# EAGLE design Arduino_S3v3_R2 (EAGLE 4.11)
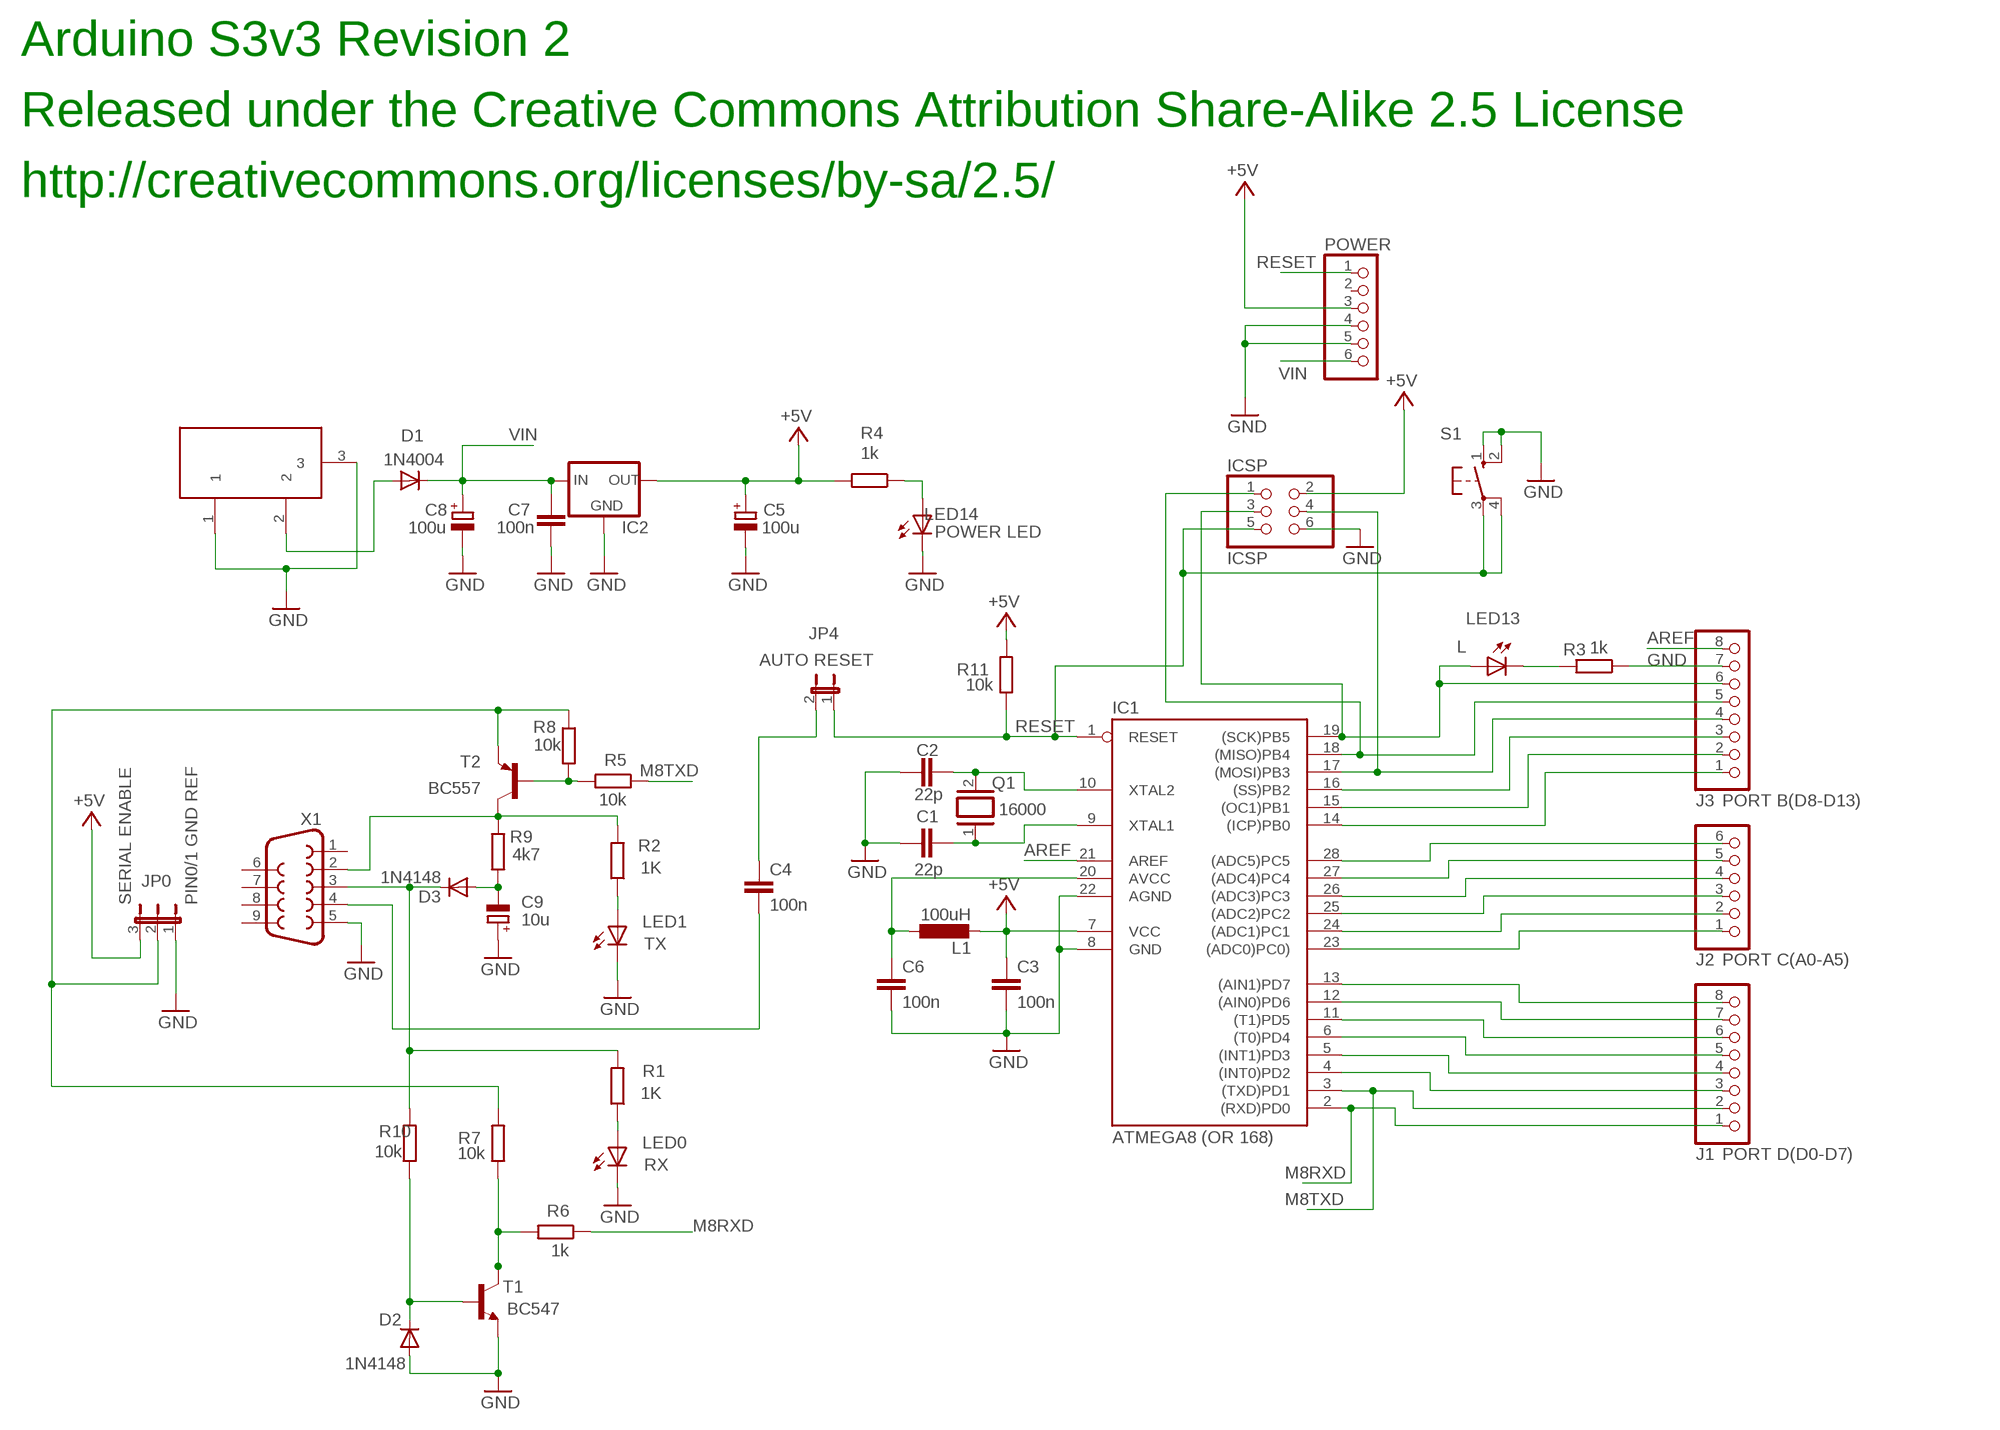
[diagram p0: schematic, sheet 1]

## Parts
C1  22p  C-EU050-025X075  [C050-025X075]
C2  22p  C-EU050-025X075  [C050-025X075]
C3  100n  C-EU050-025X075  [C050-025X075]
C4  100n  C-EU050-025X075  [C050-025X075]
C5  100u  CPOL-EUE3.5-8  [E3,5-8]
C6  100n  C-EU050-025X075  [C050-025X075]
C7  100n  C-EU050-025X075  [C050-025X075]
C8  100u  CPOL-EUE3.5-8  [E3,5-8]
C9  10u  CPOL-EUE5-6  [E5-6]
D1  1N4004  [DO41-10]
D2  1N4148  [DO35-10]
D3  1N4148  [DO35-10]
DC1  DC21MMX  [DC-21MM]
IC1  ATMEGA8 (OR 168)  AT90S4433P  [DIL28-3]
IC2  78XXL  [78XXL]
ICSP  ICSP  PINHD-2X3  [2X03]
J1  PORT D(D0-D7)  PINHD-1X8  [1X08]
J2  PORT C(A0-A5)  PINHD-1X6  [1X06]
J3  PORT B(D8-D13)  PINHD-1X8  [1X08]
JP0  JP2W  [JP2W]
JP4  AUTO RESET  JP1W  [JP1W]
L1  100uH  L-EU0207/10  [0207/10]
LED0  RX  LED3MM  [LED3MM]
LED1  TX  LED3MM  [LED3MM]
LED13  L  LED3MM  [LED3MM]
LED14  POWER LED  LED3MM  [LED3MM]
POWER  PINHD-1X6  [1X06]
Q1  16000  XTAL  [Q]
R1  1K  R-EU_0207/10  [0207/10]
R2  1K  R-EU_0207/10  [0207/10]
R3  1k  R-EU_0207/10  [0207/10]
R4  1k  R-EU_0207/10  [0207/10]
R5  10k  R-EU_0207/10  [0207/10]
R6  1k  R-EU_0207/10  [0207/10]
R7  10k  R-EU_0207/10  [0207/10]
R8  10k  R-EU_0207/10  [0207/10]
R9  4k7  R-EU_0207/10  [0207/10]
R10  10k  R-EU_0207/10  [0207/10]
R11  10k  R-EU_0207/10  [0207/10]
S1  10-XX  [B3F-10XX]
T1  BC547  [TO92]
T2  BC557  BC557B-PNP-TO92-EBC  [TO92-EBC]
X1  F09H  [F09H]

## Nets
+5V [power]: C3.1 C5.+ IC1.7(VCC) IC2.OUT ICSP.2 JP0.3 L1.2 POWER.3 R4.2 R11.2
AREF: IC1.21(AREF) J3.8
GND: C1.1 C2.1 C3.2 C5.- C6.2 C7.1 C8.- C9.+ D2.A DC1.1 DC1.3 IC1.8(GND) IC1.22(AGND) IC2.GND ICSP.6 J3.7 JP0.1 LED0.K(C) LED1.K(C) LED14.K(C) POWER.4 POWER.5 R3.1 S1.1(S) S1.2(S1) T1.1(E) X1.5
M8RXD: IC1.2((RXD)PD0) J1.1 R6.1
M8TXD: IC1.3((TXD)PD1) J1.2 R5.1
N$1: IC1.18((MISO)PB4) ICSP.1 J3.5
N$2: C9.- D3.A R9.1
N$3: LED14.A R4.1
N$4: IC1.17((MOSI)PB3) ICSP.4 J3.4
N$5: IC1.14((ICP)PB0) J3.1
N$6: C1.2 IC1.9(XTAL1) Q1.1
N$7: C2.2 IC1.10(XTAL2) Q1.2
N$8: D1.A DC1.2
N$10: IC1.4((INT0)PD2) J1.3
N$11: IC1.5((INT1)PD3) J1.4
N$12: IC1.6((T0)PD4) J1.5
N$13: IC1.11((T1)PD5) J1.6
N$14: IC1.12((AIN0)PD6) J1.7
N$15: IC1.13((AIN1)PD7) J1.8
N$16: IC1.23((ADC0)PC0)) J2.1
N$17: IC1.24((ADC1)PC1) J2.2
N$18: IC1.25((ADC2)PC2) J2.3
N$19: IC1.26((ADC3)PC3) J2.4
N$20: IC1.27((ADC4)PC4) J2.5
N$21: IC1.28((ADC5)PC5) J2.6
N$22: IC1.15((OC1)PB1) J3.2
N$23: IC1.16((SS)PB2) J3.3
N$25: D3.C R1.2 R10.2 X1.3
N$26: R6.2 R7.1 T1.3(C)
N$27: R5.2 R8.2 T2.B
N$29: D2.C R10.1 T1.2(B)
N$31: LED13.K(C) R3.2
N$32: LED1.A R2.1
N$33: LED0.A R1.1
N$34: C4.1 JP4.2
N$38: C4.2 X1.4
N$39: R2.2 R9.2 T2.C X1.2
N$42 [power]: C6.1 IC1.20(AVCC) L1.1
RESET: IC1.1(RESET) ICSP.5 JP4.1 POWER.1 R11.1 S1.3(P) S1.4(P1)
SCK: IC1.19((SCK)PB5) ICSP.3 J3.6 LED13.A
SERIAL_VCC: JP0.2 R7.2 R8.1 T2.E
VIN [power]: C7.2 C8.+ D1.C IC2.IN POWER.6
Unconnected: POWER.2 X1.1 X1.6 X1.7 X1.8 X1.9

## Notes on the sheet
- Arduino S3v3 Revision 2
- Released under the Creative Commons Attribution Share-Alike 2.5 License
- http://creativecommons.org/licenses/by-sa/2.5/
- SERIAL ENABLE | PIN0/1 GND REF

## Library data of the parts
C1-C4 C6 C7 = rcl:C-EU: CAPACITOR, European symbol
C5 C8 C9 = rcl:CPOL-EU: POLARIZED CAPACITOR, European symbol
D1 = diode:1N4004: DIODE
D2 D3 = diode:1N4148: DIODE
DC1 = powersupply:DC21MM
IC1 = atmel:AT90S4433: MICROCONTROLLER 4 Kbytes FLASH 128 bytes SRAM 256 bytes EEPROM UART 6-channel 10 bit ADC
IC2 = v-reg:78XXL: VOLTAGE REGULATOR
ICSP = pinhead:PINHD-2X3: PIN HEADER
J1 J3 = pinhead:PINHD-1X8: PIN HEADER
J2 POWER = pinhead:PINHD-1X6: PIN HEADER
JP0 = jumper:JP2W: JUMPER
JP4 = jumper:JP1W
L1 = rcl:L-EU: INDUCTOR, European symbol
LED0 LED1 LED13 LED14 = led:LED: LED
Q1 = special:XTAL: CRYSTAL
R1-R11 = rcl:R-EU_: RESISTOR, European symbol
S1 = switch-omron:10-XX: OMRON SWITCH
T1 = transistor:BC547: NPN TRANSISTOR
T2 = transistor:*-PNP-: PNP Transistror
X1 = con-subd:F09: SUB-D

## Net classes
1 power: width 0.61 mm

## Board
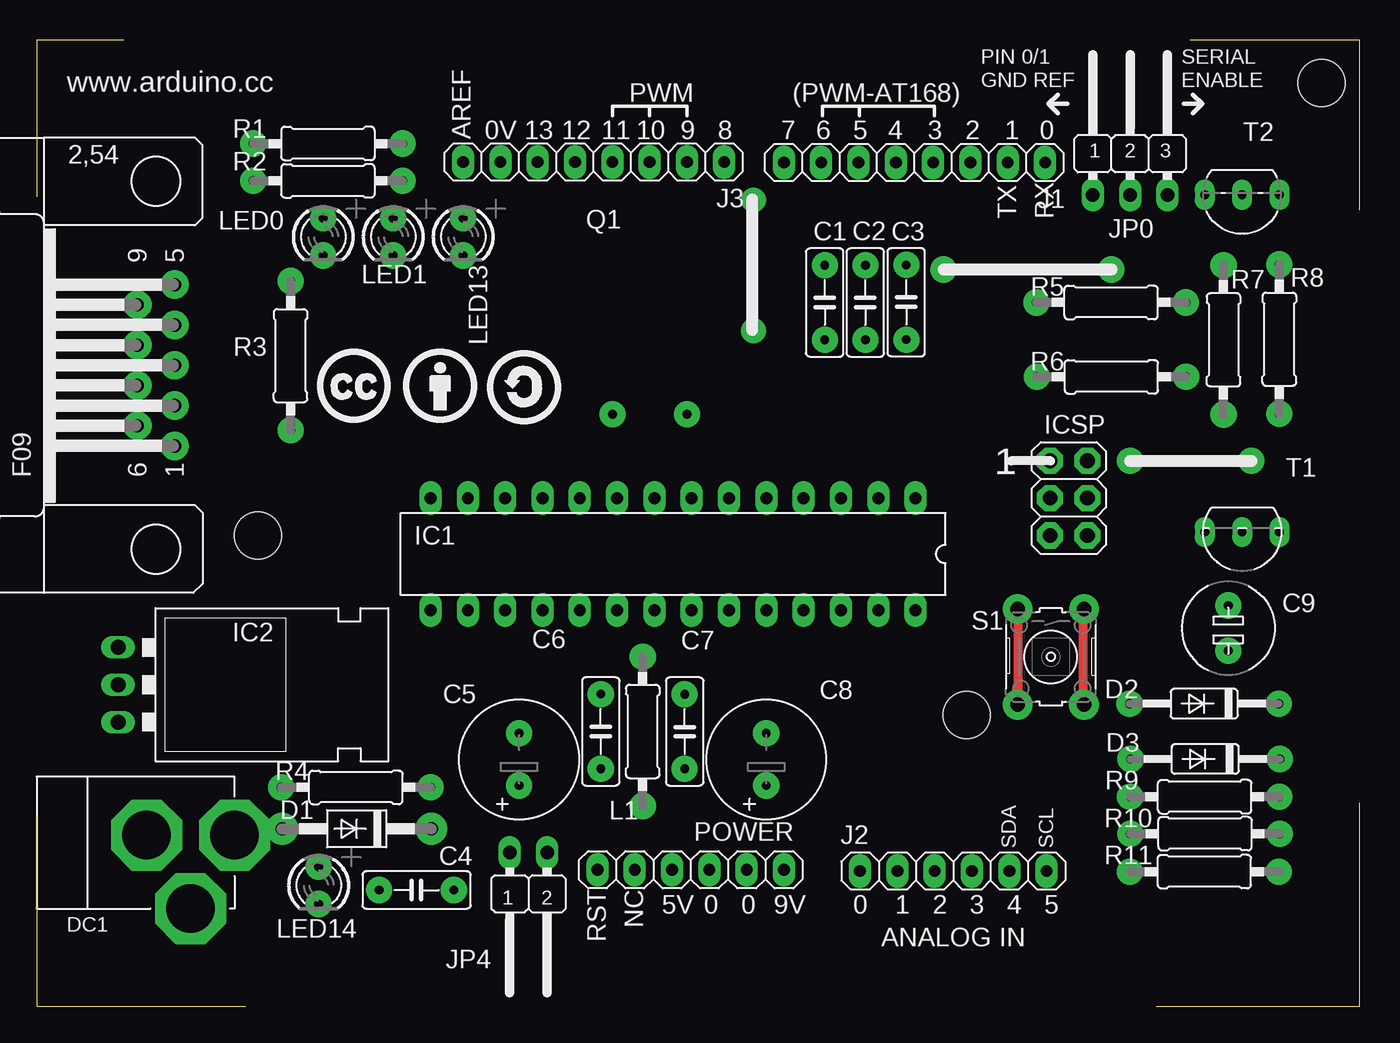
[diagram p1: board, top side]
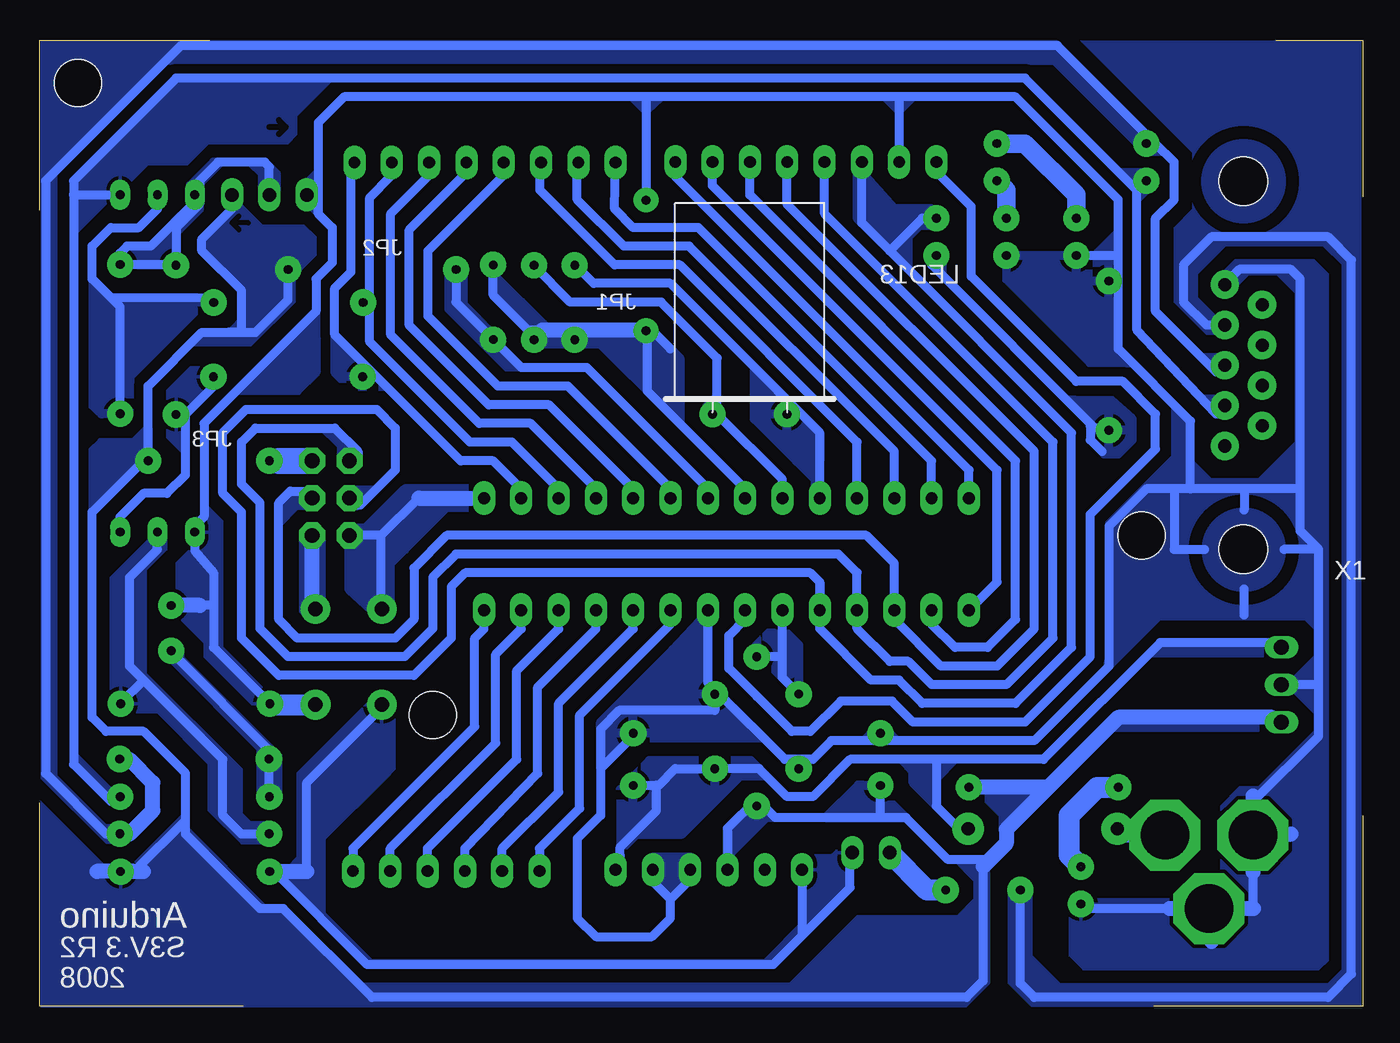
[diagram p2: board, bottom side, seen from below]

Size 90.06 x 65.74 mm. Coordinates in mm from the lower left corner, seen from the top.
Outline: 0.01,65.74 0.01,55.07
Outline: 0.01,12.95 0.01,0 14.23,0
Outline: 76.2,0 90.06,0
Outline: 90.05,65.73 78.5,65.73
Outline: 5.91,65.74 0,65.74
Outline: 90.06,0.01 90.06,13.85
Outline: 90.05,54.18 90.05,65.73
Copper layers (1*16): Top 0.035mm / dielectric 1.5mm / Bottom 0.035mm
Design rules "gizmo": minimum track width 0.6mm, minimum drill 0.6mm, track to track 0.67mm, track to pad 0.67mm, pad to pad 0.67mm, via to via 0.67mm, smd to smd 0mil, copper to edge 0mil, drill to drill 8mil, minimum pad ring 10mil, minimum via ring 8mil, stop-mask expansion 0mil, vias tented up to drill 0mil, thermal gap 10mil
Holes 3.2 mm at 87.45,62.83 63.32,19.81 15.06,32.03
bRestrict: 6 lines

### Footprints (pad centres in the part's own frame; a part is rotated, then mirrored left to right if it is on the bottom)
C050-025X075 = drill 0.6 pad 1.778 round: 1 -2.54,0; 2 2.54,0
E3,5-8 = drill 0.6 pad 1.778 round: + -1.778,0; - 1.778,0
E5-6 = drill 0.6 pad 1.778 round: + -1.54,0; - 1.54,0
DO41-10 = drill 0.9 pad 2.159 round: A 5.08,0; C -5.08,0
DO35-10 = drill 0.6 pad 1.778 round: A 5.08,0; C -5.08,0
DC-21MM = drill 3.302 pad 4.826 octagon: 1 -5.08,-3.353; 2 -0.076,-6.35; 3 -0.076,-0.356
DIL28-3 = drill 0.813 pad 1.524 long: 1 -16.51,-3.81; 2 -13.97,-3.81; 3 -11.43,-3.81; 4 -8.89,-3.81; 5 -6.35,-3.81; 6 -3.81,-3.81; 7 -1.27,-3.81; 8 1.27,-3.81; 9 3.81,-3.81; 10 6.35,-3.81; 11 8.89,-3.81; 12 11.43,-3.81; 13 13.97,-3.81; 14 16.51,-3.81; 15 16.51,3.81; 16 13.97,3.81; 17 11.43,3.81; 18 8.89,3.81; 19 6.35,3.81; 20 3.81,3.81; 21 1.27,3.81; 22 -1.27,3.81; 23 -3.81,3.81; 24 -6.35,3.81; 25 -8.89,3.81; 26 -11.43,3.81; 27 -13.97,3.81; 28 -16.51,3.81
78XXL = drill 1.016 long: GND 0,-3.81; IN -2.54,-3.81; OUT 2.54,-3.81
2X03 = drill 1 pad 1.778 octagon: 1 -2.54,-1.27; 2 -2.54,1.27; 3 0,-1.27; 4 0,1.27; 5 2.54,-1.27; 6 2.54,1.27
1X08 = drill 0.8 pad 1.524 long: 1 -8.89,0; 2 -6.35,0; 3 -3.81,0; 4 -1.27,0; 5 1.27,0; 6 3.81,0; 7 6.35,0; 8 8.89,0
1X06 = drill 0.8 pad 1.524 long: 1 -6.35,0; 2 -3.81,0; 3 -1.27,0; 4 1.27,0; 5 3.81,0; 6 6.35,0
JP2W = drill 0.914 pad 1.524 long: 1 -2.54,-1.27; 2 0,-1.27; 3 2.54,-1.27
JP1W = drill 0.914 pad 1.524 long: 1 -1.27,-1.905; 2 1.27,-1.905
0207/10 = drill 0.6 pad 1.778 round: 1 -5.08,0; 2 5.08,0
LED3MM = drill 0.6 pad 1.778 round: A -1.27,0; K 1.27,0
Q = drill 0.6 pad 1.778 round: 1 -2.54,-7.62; 2 2.54,-7.62
B3F-10XX = drill 1 pad 2.032 round: 1 -3.251,2.261; 2 3.251,2.261; 3 -3.251,-2.261; 4 3.251,-2.261
TO92 = drill 0.6 pad 1.372 long: 1 2.54,0; 2 0,0; 3 -2.54,0
TO92-EBC = drill 0.6 pad 1.372 long: B 0,-1.27; C -2.54,-1.27; E 2.54,-1.27
F09H = drill 0.9 pad 1.93 round: 1 -5.486,-1.27; 2 -2.743,-1.27; 3 0,-1.27; 4 2.743,-1.27; 5 5.486,-1.27; 6 -4.115,1.27; 7 -1.372,1.27; 8 1.372,1.27; 9 4.115,1.27 | hole 3.302: -12.522,0; 12.522,0

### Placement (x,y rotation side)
C1  56.41,47.88 90 top
C2  53.65,47.88 90 top
C3  59.2,47.9 90 top
C4  25.86,7.9 180 top
C5  32.84,16.79 90 top
C6  38.4,18.7 270 top
C7  44.11,18.69 270 top
C8  49.67,16.79 90 top
C9  81.11,25.73 270 top
D1  21.79,12.07 180 top
D2  79.48,20.58 180 top
D3  79.54,16.81 180 top
DC1  7.12,11.71 90 top
IC1  43.32,30.76 180 top
IC2  9.35,21.87 270 top
ICSP  70.25,34.57 270 top
J1  59.75,57.41 180 top
J2  62.4,9.2 0 top
J3  37.91,57.45 180 top
JP0  74.43,56.48 0 top
JP4  33.48,8.54 180 top
L1  41.25,18.7 270 top
LED0  19.51,52.35 270 top
LED1  24.27,52.35 270 top
LED13  29.03,52.35 270 top
LED14  19.19,8.22 270 top
POWER  44.52,9.28 0 top
Q1  41.73,47.91 0 bottom
R1  19.82,58.7 180 top
R2  19.82,56.16 180 top
R3  17.28,44.26 270 top
R4  21.73,14.89 0 top
R5  73.14,47.89 0 top
R6  73.16,42.83 0 top
R7  80.79,45.34 90 top
R8  84.59,45.39 270 top
R9  79.51,14.25 0 top
R10  79.53,11.74 0 top
R11  79.49,9.16 0 top
S1  69.04,23.77 270 top
T1  82.06,32.26 180 top
T2  82.05,53.95 180 top
U$1  [CC]  19.03,39.65 0 top
U$2  [BY]  24.9,39.65 0 top
U$3  [SA]  30.62,39.65 0 top
X1  8.12,43.61 90 top

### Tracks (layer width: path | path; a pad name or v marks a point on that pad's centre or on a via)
+5V  (via drill 0.6 pad 1.78, 0.61 pad 1.78)
  Top 0.6: v73.16,50.13 v61.73,50.13 | v82.69,37.11 v74.43,37.11
  Bottom 0.6: 80.15,12.66 80.15,15.84 83,18.7 85.55,18.7 86.5,19.65 86.5,33.62 83,37.11 v82.69,37.11 82.69,42.19 79.04,45.84 76.34,45.84 | v74.43,37.11 73.8,37.11 v74.43,37.11 | POWER.3 43.25,12.1 41.25,14.09 | IC2.OUT 6.17,19.65 | 80.15,12.66 83.64,9.17 | C3.1 57.29,43.46 52.84,43.46 44.59,35.21 | C3.1 61.73,47.91 v61.73,50.13 | 80.15,12.66 80.15,11.71 75.07,6.63 73.48,6.63 67.45,0.6 26.97,0.6 25.85,1.71 25.85,9.49 25.85,9.97 28.24,9.97 31.09,12.82 | JP0.3 76.97,54.26 79.04,52.19 79.04,51.4 76.34,48.7 76.34,45.84 | v73.16,50.13 73.16,48.07 75.38,45.84 76.34,45.84 | 76.34,45.84 77.29,45.84 | R4.2 | 31.09,12.82 | C3.1 59.19,45.53 C3.1 | 44.59,35.21 | 41.25,14.09 | 31.09,12.82 32.84,12.82 | 32.84,12.82 39.98,12.82 41.25,14.09 | C5.+ 32.84,12.82 | 44.59,35.21 IC1.7
  Bottom 1.016: 21.41,14.89 16.65,19.65 6.17,19.65 | 21.41,14.89 24.27,12.03 24.27,11.08 25.85,9.49 | 83,9.17 83.64,9.17 86.18,9.17 | 21.41,14.89 R4.2
  Bottom 1.778: 73.8,37.11 ICSP.2
  pour Bottom: 25.38,1.55 25.38,9.97 27.13,9.97 27.92,9.97 26.49,8.54 26.49,7.27 27.6,6.16 34.43,6.16 39.03,1.55 68.4,1.55 73.48,6.63 74.43,6.63 80.15,12.35 80.15,13.3 83.64,9.81 84.59,9.81 85.23,9.17 89.99,13.94 89.99,-0.04 26.97,-0.04
  pour Bottom (no thermals): 7.12,18.7 17.6,18.7 16.65,19.65 7.12,19.65
  pour Bottom: 71.26,52.35 71.26,51.08 72.69,49.65 72.69,47.91 75.7,44.89 79.99,44.89 78.88,46 77.29,46 76.18,47.11 76.18,48.54 78.72,51.08 78.72,51.08 79.04,51.4 79.04,52.35 74.91,52.35
  pour Bottom: 86.5,33.62 86.5,37.75 85.86,38.38 83.64,38.38 82.69,39.34 82.69,37.43
  pour Bottom (no thermals): 72.05,53.15 74.91,53.15 76.34,54.58 76.81,54.58 79.04,52.35 71.26,52.35
  pour Bottom (no thermals): 59.19,45.37 57.29,43.46 58.24,43.46 62.21,47.43 62.21,50.13 61.26,50.13 61.26,47.75 59.19,45.69
  pour Bottom: 31.09,12.82 33.32,15.05 34.35,15.05 36.57,12.82
  pour Bottom (no thermals): 39.98,12.82 40.62,12.82 43.24,10.2 43.24,12.11 41.25,14.09
  pour Bottom: 24.27,12.03 24.27,13.14 26.01,14.89 21.41,14.89
AREF
  Bottom 0.6: IC1.21 42.05,26.64 42.05,26.32 43.16,25.21 43.16,22.98 41.25,21.08 38.87,18.7 37.6,18.7 35.54,20.76 32.05,20.76 30.62,19.33 23,19.33 18.55,23.78 18.55,33.46 14.11,37.91 14.11,40.29 16.33,42.51 19.5,42.51 26.65,49.65 26.65,54.42 28.71,56.48 28.71,57.43 J3.8
GND  (via drill 0.6 pad 1.68, 1 pad 2.03)
  Top 0.6: 48.72,54.85 48.72,45.96 v48.79,45.96 | 48.72,54.85 48.72,54.89 | v48.79,54.85 48.72,54.85 | 71.26,20.6 S1.2 | 71.26,20.6 71.26,26.95 S1.1 | S1.2 71.26,20.6
  Bottom 0.6: D2.A 74.41,20.52 | 74.39,20.56 D2.A | 74.39,20.56 78.24,24.41 78.24,27.27 | 79.51,32.67 78.88,33.3 78.88,39.65 71.26,47.27 71.26,49.5 70.15,50.61 70.15,52.99 71.1,53.94 | 79.51,32.67 79.51,31 78.24,29.49 78.24,27.27 | 42.05,35.21 | 42.05,35.21 48.72,41.87 48.72,46 48.75,46 v48.79,45.96 | 48.79,61.88 v48.79,54.85 | X1.5 9.39,49.13 8.39,50.13 4.9,50.13 4.26,49.49 4.26,35.21 | 11.73,35.21 11.73,39.81 16.65,44.73 16.65,51.08 | 16.65,51.08 16.65,54.89 23.63,61.88 31.57,61.88 | J3.7 31.57,57.12 31.57,61.88 | 31.57,61.88 48.79,61.88 | 4.26,35.21 8.07,35.21 | 8.07,35.21 11.73,35.21 | 11.73,35.21 12.84,35.21 | 2.99,21.87 2.99,31.08 | 2.99,31.08 4.26,32.35 4.26,35.21 | 78.24,27.27 79.16,27.27 | 13.16,6.64 10.5,6.64 | 13.16,6.64 13.47,6.63 19.19,6.64 LED14.K | 44.11,20.13 50.62,20.13 51.89,18.86 51.89,16.16 | 51.89,16.16 51.89,12.98 53.48,11.4 53.48,6 52.21,4.73 48.4,4.73 47.13,6 47.13,7.27 | 2.99,21.87 IC2.GND | 10.3,6.63 13.16,6.64 | 7.44,6.63 7.44,11.71 7.47,13.62 | 2.99,21.87 2.99,18.38 7.44,13.94 7.47,13.62 | 7.47,13.62 7.48,14.29 | D2.A 74.43,20.58 74.43,20.6 74.39,20.56 | 74.39,20.56 74.35,20.52 | 71.3,26.95 71.26,26.95 71.52,27.22 | 47.13,7.27 48.4,8.54 48.4,9.17 48.33,9.17 POWER.5 | POWER.4 45.79,8.61 47.13,7.27 | 16.65,51.08 LED0.K | 47.13,44.73 48.4,46 | 48.79,61.88 69.35,61.88 71.1,60.13 71.1,53.94 | 71.1,53.94 71.1,55.21 JP0.1 | T1.1 79.53,32.67 79.51,32.67 | 12.84,35.21 14.74,35.21 17.28,32.67 17.28,23.14 22.36,18.06 32.84,18.06 | 12.84,35.21 12.84,31.08 10.77,31.08 | 2.99,31.08 5.38,31.08 | 8.07,35.21 8.07,33.78 | 8.07,26.64 8.07,28.38 | 32.84,18.06 36.17,18.06 37.44,16.79 38.4,16.79 C6.2 38.4,16.79 39.34,16.79 43.95,21.4
  Bottom 0.6: C5.- 32.84,18.06 | 55.86,46 56.81,46 59.19,48.39 59.19,50.13 59.19,50.28 C3.2 | 43.95,21.4 44.43,21.87 44.46,21.87 44.11,20.6 44.11,20.13 | C7.1 44.11,20.92 44.11,20.13 | C8.- 49.67,18.38 51.89,16.16 | 43.95,21.4 | IC1.22 44.59,22.03 43.95,21.4 | 53.64,46 53.64,45.84 53.65,45.83 C2.1 | 42.05,35.21 IC1.8
  Bottom 1.016: 79.16,27.27 C9.+ | 7.48,14.29 7.48,9.11 | S1.1 71.3,26.95 | 71.52,27.22 ICSP.6 | 4.9,11.71 7.44,11.71 9.35,11.71 | 7.44,6.63 10.3,6.63 | 10.3,6.63 13.16,6.63 | 10.3,6.63 10.3,4.41 | 56.49,45.37 55.87,45.99 | 55.87,45.99 55.86,46 | 48.72,46 53.64,46 55.87,45.99
  Bottom 1.422: 74.35,20.52 S1.2
  other vias: 71.3,20.52
  pour Bottom: 11.25,7.27 16.65,7.27 16.65,2.5 3,2.5 2.36,3.14 2.36,49.81 3.31,50.77 8.71,50.77 7.76,49.81 5.85,49.81 4.58,48.54 4.58,38.38 7.12,35.84 10.3,35.84 11.73,37.27 11.73,39.81 13,41.08 13,37.43 17.6,32.83 17.6,22.51 13.79,26.32 3.95,26.32 3.31,25.68 3.31,18.7 7.12,14.89 8.39,14.89 9.66,13.62 9.66,8.86
  pour Bottom: 46.49,44.1 46.49,39.65 52.84,46 48.4,46
  pour Bottom: 47.76,61.88 48.79,60.92 49.75,61.88
  pour Bottom: 30.62,61.88 31.57,60.92 32.52,61.88
  pour Bottom (no thermals): 45.7,10.12 48.4,10.12 48.4,8.86 47.13,7.58 45.7,9.01
  pour Bottom: 16.65,7.27 19.98,7.27 19.98,3.46 19.03,2.5 16.65,2.5
  pour Bottom (no thermals): 4.58,22.51 2.68,24.41 2.68,19.33 4.58,21.24
  pour Bottom (no thermals): 70.62,31.71 70.62,26.79 70.78,26.64 72.21,26.64 72.37,26.79 72.37,31.71
  pour Bottom (no thermals): 7.76,49.81 8.71,48.86 9.66,49.81 8.71,50.77
  pour Bottom: 24.27,51.08 24.27,49.49 18.55,43.78 15.7,43.78 16.65,44.73 16.65,52.67 18.24,51.08
  pour Bottom: 74.43,21.24 77.61,24.41 77.61,32.98 78.88,34.25 78.88,32.03 80.78,30.13 80.78,26.64 78.88,24.73 78.88,23.78 75.39,20.29 74.43,20.29
  pour Bottom: 71.26,47.27 71.26,43.14 72.53,41.88 76.66,41.88
  pour Bottom (no thermals): 72.21,56 71.26,56.96 71.26,53.78 72.21,54.73
  pour Bottom (no thermals): 59.19,49.81 55.54,46.16 52.84,46.16 51.73,45.05 55.86,45.05 59.19,48.38
  pour Bottom: 51.89,19.33 46.97,24.25 44.59,24.25 44.59,22.03 40.78,18.22 49.83,18.22 51.89,16.16
  pour Bottom (no thermals): 46.97,24.25 44.59,26.79 44.59,24.25
  pour Bottom (no thermals): 32.84,19.17 31.73,18.06 33.95,18.06
M8RXD
  Bottom 0.6: IC1.2 57.29,35.21 59.19,37.11 61.41,37.11 67.76,43.46 | 67.76,43.46 R6.1 | 67.76,43.46 69.99,45.69 69.99,48.86 68.88,49.97 68.88,56.96 68.64,57.36 J1.1
  pour Bottom: 69.99,45.69 69.99,43.15 69.04,42.19 66.5,42.19
M8TXD
  Bottom 0.6: IC1.3 54.75,35.21 57.92,38.38 60.78,38.38 67.29,44.89 67.61,45.21 67.61,47.91 | J1.2 66.1,56.55 66.18,56.48 67.61,55.03 67.61,47.91 | R5.1 68.04,47.91 67.61,47.91
N$1
  Bottom 0.6: ICSP.1 68.4,37.11 68.4,37.75 69.99,39.34 75.39,39.34 76.34,38.38 76.34,35.52 75.07,34.25 75.07,25.68 73.16,23.78 65.23,23.78 63.32,25.68 63.32,29.18 61.73,30.76 35.7,30.76 34.43,29.49 IC1.18 34.43,25.68 32.21,23.46 30.93,23.46 29.35,21.87 24.27,21.87 21.09,25.05 21.09,38.38 36.64,53.93 J3.5
  pour Bottom (no thermals): 68.4,37.43 68.4,37.75 69.99,39.34 71.1,39.34 69.83,38.06 69.83,37.43
N$2
  Bottom 0.6: C9.- 80.79,23.79 74.43,17.43 74.43,16.81 | R9.1 | R9.1 74.45,14.26 | 74.43,16.81 D3.A | R9.1 74.43,16.81
  pour Bottom (no thermals): 75.23,14.41 75.23,17.43 81.26,23.46 80.31,24.41 80.31,23.78 73.64,17.11 73.64,14.41
N$3  (1 unrouted)
  Bottom 0.6: R4.1
  Bottom 1.422: R4.1 18.08,14.89 19.98,12.98 19.98,10.28 LED14.A
N$4
  Bottom 0.6: ICSP.4 71.58,35.05 73,35.05 73.8,34.25 73.8,26.32 72.53,25.05 65.86,25.05 64.59,26.32 64.59,29.81 62.37,32.03 33.79,32.03 31.89,30.13 IC1.17 31.89,26.32 28.71,23.14 24.9,23.14 22.36,25.68 22.36,37.75 39.18,54.57 J3.4
  pour Bottom (no thermals): 71.89,33.78 72.53,33.78 73.64,32.67 73.64,34.25 73,34.89 72.37,34.89 71.89,35.37
N$5
  Bottom 0.6: IC1.14 26.81,36.48 46.81,56.48 46.81,57.12 J3.1
N$6
  Bottom 0.6: IC1.9 39.51,35.84 43.95,40.29 | 43.95,40.29 Q1.1 | 43.95,40.29 43.95,44.1 47.76,47.91 53.95,47.91 56.49,50.45 C1.2
  pour Bottom (no thermals): 44.27,39.65 43,39.65 43.95,40.6 43.95,41.88 44.91,40.92 44.91,40.29
N$7
  Bottom 0.6: 38.87,40.92 39.83,41.88 | 38.87,40.92 47.13,49.18 52.37,49.18 53.64,50.45 53.65,50.45 C2.2 | IC1.10 36.97,39.02 38.87,40.92 | 38.87,40.92 Q1.2
  pour Bottom: 36.97,37.11 38.56,37.11 41.41,39.97 41.41,43.46 36.97,39.02
  pour Bottom (no thermals): 38.56,37.11 37.29,35.84 37.29,35.05 36.97,35.05 36.97,37.11
N$8
  Bottom 0.6: 16.65,12.03 16.65,12.07
  Bottom 1.016: 16.65,12.07 D1.A | DC1.2 16.25,11.64 16.65,12.03
N$10
  Bottom 0.6: IC1.4 52.21,35.21 56.65,39.65 60.15,39.65 66.18,45.68 66.18,53.94 63.64,56.48 63.64,57.43 J1.3
N$11
  Bottom 0.6: IC1.5 49.67,35.21 55.38,40.92 59.51,40.92 64.91,46.32 64.91,52.83 61.1,56.64 61.1,57.43 J1.4
N$12
  Bottom 0.6: IC1.6 47.13,35.21 54.11,42.19 58.87,42.19 63.64,46.95 63.64,51.4 58.56,56.48 58.56,57.43 J1.5
N$13
  Bottom 0.6: IC1.11 34.43,38.38 46.49,50.45 50.94,50.45 56.02,55.53 56.02,57.41 | 56.02,57.41 56.02,57.43 | 56.02,57.41 J1.6
N$14
  Bottom 0.6: IC1.12 31.89,37.75 45.86,51.72 50.3,51.72 53.48,54.89 53.48,57.41 | 53.48,57.41 53.48,57.43 | 53.48,57.41 J1.7
N$15
  Bottom 0.6: IC1.13 29.35,37.11 45.22,52.99 49.67,52.99 50.94,54.26 J1.8
N$16
  Bottom 0.6: IC1.23 47.13,26 53.32,19.81 53.32,13.46 56.05,10.73 J2.1
N$17
  Bottom 0.6: IC1.24 49.67,25.68 54.75,20.6 54.75,14.57 58.59,10.73 J2.2
N$18
  Bottom 0.6: IC1.25 52.21,25.68 56.18,21.71 56.18,15.84 61.13,10.73 J2.3
N$19
  Bottom 0.6: IC1.26 54.75,25.68 57.61,22.82 57.61,16.79 63.67,10.73 J2.4
N$20
  Bottom 0.6: IC1.27 57.29,25.68 59.03,23.94 59.03,17.9 66.21,10.73 J2.5
N$21
  Bottom 0.6: IC1.28 59.83,25.68 60.46,25.05 60.46,19.02 68.75,10.73 J2.6
N$22
  Bottom 0.6: IC1.15 24.9,28.86 24.9,36.48 44.27,55.84 44.27,57.12 J3.2
N$23
  Bottom 0.6: IC1.16 29.35,26 27.76,24.41 25.54,24.41 23.63,26.32 23.63,37.11 41.73,55.21 41.73,57.12 | 41.73,57.12 41.73,57.43 | 41.73,57.12 J3.3
N$25
  Bottom 0.6: 83.93,11.74 R10.2 83.96,11.71 | D3.C 84.59,16.79 83.96,16.79 | 84.59,11.71 85.55,11.71 89.67,15.84 89.67,56.16 80.47,65.37 20.77,65.37 14.11,58.7 | X1.3 9.35,43.3 9.35,43.15 9.98,43.15 14.11,47.27 14.11,53.62 12.84,54.89 12.84,57.43 14.11,58.7 | 14.11,58.7 R1.2
  Bottom 1.016: 83.93,11.74 82.37,13.3 82.37,15.2 83.96,16.79 | 84.59,11.71 83.96,11.71
  pour Bottom (no thermals): 84.91,12.35 85.55,12.35 88.88,15.68 88.88,56.96 81.74,64.1 21.09,64.1 14.9,57.91 13,57.91 20.78,65.69 89.99,65.69 89.99,15.52 85.55,11.08 84.91,11.08
  pour Bottom (no thermals): 11.25,44.41 9.35,44.41 9.35,43.15 9.98,43.15
N$26
  Bottom 0.6: T1.3 84.6,32.66 84.59,33.3 83,34.89 81.42,34.89 80.15,36.16 80.15,40.29 | 80.15,40.29 78.24,42.19 R6.2 | R7.1 80.77,40.29 80.15,40.29
  pour Bottom: 78.24,42.19 78.24,43.46 79.83,43.46 81.42,41.88 81.42,38.7 80.15,37.43 80.15,40.29
N$27
  Bottom 0.6: R5.2 78.58,48.2 85.23,48.23 | R8.2 84.59,40.29 R8.2 | 85.23,48.23 84.59,47.59 R8.2 | 85.23,48.23 86.5,49.49 86.5,51.72 85.23,52.99 83.32,52.99 82.05,54.26 T2.B
  pour Bottom: 78.24,48.23 78.24,47.59 79.2,47.59 83.96,42.83 83.96,40.6 84.59,39.97 85.55,39.97 86.5,40.92 86.5,49.49 85.23,48.23
N$29
  Bottom 0.6: R10.1 74.75,11.71 76.34,11.71 77.61,12.98 77.61,16.79 83,22.19 | T1.2 82.06,31.07 83.96,29.18 83.96,23.14 83,22.19 | D2.C 84.55,20.64 83,22.19
  pour Bottom: 82.85,29.65 82.85,22.67 76.34,16.16 76.34,11.08 78.56,13.3 78.56,16.48 82.05,19.97 84.91,19.97 85.23,20.29 85.23,29.18
  pour Bottom (no thermals): 82.85,29.65 81.42,31.08 81.42,32.03 82.37,32.03 85.23,29.18
  pour Bottom (no thermals): 76.34,11.08 74.75,11.08 74.75,12.51 75.7,12.51 76.34,13.14
N$31
  Bottom 0.6: 18.24,39.34 29.35,50.45 29.35,51.08 LED13.K | R3.2 | R3.2 | R3.2 17.28,39.34 18.24,39.34 | 17.76,37.75 18.55,38.54 18.55,39.49 18.39,39.34 18.24,39.34
  pour Bottom (no thermals): 28.4,51.08 28.4,49.49 29.35,50.45 29.35,51.08
  pour Bottom: 15.7,38.54 15.7,39.97 17.12,41.24 20.14,41.24 18.55,39.65 18.55,38.54 17.6,37.59 16.65,37.59
N$32
  Bottom 1.27: LED1.A 24.27,55.53 R2.1
N$33
  Bottom 1.27: LED0.A 19.5,55.21 23,58.7 R1.1
N$34
  Bottom 1.422: C4.1 29.67,7.9 JP4.2
N$38
  Bottom 0.6: X1.4 10.65,46.36 12.2,47.91 12.2,50.45 10.3,52.35 2.36,52.35 0.77,50.77 0.77,2.19 2.36,0.6 22.36,0.6 23.32,1.55 C4.2 | C4.2
  pour Bottom (no thermals): 22.52,7.9 22.52,3.46 20.62,1.55 2.36,1.55 1.41,2.5 1.41,50.45 2.68,51.72 9.35,51.72 11.25,49.81 11.25,48.23 9.98,46.95 9.66,46.95 9.98,46.64 9.98,46 9.66,45.69 10.62,45.69 12.84,47.91 12.84,52.99 11.57,54.26 11.57,58.07 19.19,65.69 0.14,65.69 0.14,-0.04 22.52,-0.04 24.11,1.55 24.11,7.9
N$39
  Bottom 0.6: 84.59,13.94 85.23,13.94 87.77,16.46 87.77,55.21 | 84.59,13.94 84.61,14.26 | 15.38,55.53 23,63.15 80.78,63.15 87.77,56.16 87.77,55.21 | 15.38,55.53 15.38,46 9.98,40.29 9.35,40.29 9.35,40.55 X1.2 | 15.38,55.53 R2.2 | R9.2 85.23,14.25 84.59,13.94 | T2.C 87.76,55.22 87.77,55.21
  pour Bottom (no thermals): 14.58,56.96 16.97,56.96 15.54,55.53 15.54,54.42 14.58,55.37
  pour Bottom (no thermals): 9.35,41.56 11.25,41.56 9.98,40.29 9.35,40.29
  pour Bottom (isolate 0.254, no thermals): 84.91,14.57 87.77,17.43 87.77,16.48 85.55,14.25 84.91,14.25
  pour Bottom (isolate 0.025): 83.96,55.21 83.96,56 82.69,57.27 79.99,57.27 78.56,58.7 73.16,58.7 72.53,59.34 72.53,60.61 69.99,63.15 80.78,63.15 87.77,56.16 87.77,52.35 84.91,55.21
N$42
  Bottom 0.6: 39.51,23.78 39.51,22.35 C6.1 | 39.51,23.78 IC1.20 | 39.51,23.78 | 39.51,23.78 L1.1
  pour Bottom: 38.4,21.24 38.4,24.57 39.51,25.68 39.51,26.32 41.41,24.41 41.41,24.25
RESET
  Top 0.6: S1.3 66.81,26.95 66.81,20.6 S1.4
  Bottom 0.6: 66.81,32.03 64.27,34.57 | 66.81,32.03 ICSP.5 | 34.9,8.06 38.08,4.89 38.14,4.95 38.14,8.22 POWER.1 | 71.89,9.17 71.89,15.2 66.81,20.28 66.81,20.6 S1.4 | 74.43,9.17 74.43,9.16 R11.1 | S1.3 66.78,26.95 66.81,26.95 66.81,32.03 | 34.9,8.06 40.14,2.82 67.76,2.82 74.11,9.17 | 34.9,8.06 34.9,9.81 34.9,10.44 JP4.1
  Bottom 1.016: 64.27,34.57 IC1.1 | 71.89,9.17 74.11,9.17 74.43,9.17
  pour Bottom: 72.53,15.52 72.53,10.12 73.16,9.49 74.43,9.49 67.77,2.82 40.14,2.82 34.75,8.22 34.75,11.08 35.38,11.08 36.17,10.28 38.08,10.28 38.08,5.84 40.78,3.14 67.45,3.14 70.62,6.32 70.62,11.39 66.5,15.52
  pour Bottom: 65.23,31.08 62.37,33.94 60.15,33.94 60.15,35.21 65.23,35.21
  pour Bottom: 66.5,15.52 65.86,16.16 65.86,20.6 67.77,20.6 72.53,15.84 72.53,15.52
  pour Bottom (no thermals): 65.23,35.21 67.92,32.51 69.04,32.51 69.04,28.38 67.13,26.64 66.18,26.64 66.18,30.13 65.23,31.08
SCK
  Bottom 0.6: 36.97,28.86 IC1.19 | 36.97,28.86 37.6,29.49 61.1,29.49 62.05,28.54 62.05,25.05 64.59,22.51 73.8,22.51 76.34,25.05 76.34,33.62 77.61,34.89 77.61,39.02 76.02,40.6 67.13,40.6 65.86,39.34 65.86,36.48 67.76,34.57 68.24,34.1 68.88,34.1 68.88,34.57 ICSP.3 | 36.97,28.86 36.97,25.68 33.48,22.19 31.57,22.19 29.98,20.6 23.63,20.6 19.82,24.41 19.82,39.02 32.21,51.4 | 32.21,51.4 34.11,53.3 | J3.6 34.11,57.43 34.11,53.3 | 34.11,53.3 34.11,53.62 | LED13.A 29.98,53.62 32.21,51.4
  pour Bottom (no thermals): 30.94,50.13 30.94,52.35 30.14,53.15 29.03,53.15 29.03,53.94 29.35,54.26 31.89,54.26 34.43,57.12 34.43,53.62
  pour Bottom (no thermals): 68.4,33.78 66.81,35.37 69.35,35.37 69.35,33.78
SERIAL_VCC
  Bottom 0.6: 84.59,50.45 R8.1 | 80.82,50.45 R7.2 80.79,50.45 80.78,50.45 | 79.19,55.05 T2.E 79.19,55.21 79.2,55.21 79.2,56.16 77.92,57.43 74.75,57.43 74.43,57.12 JP0.2 | 79.19,55.05 79.19,54.58 80.78,52.99 80.78,50.45 | 84.59,50.45 84.59,51.24 84.12,51.72 82.53,51.72 79.2,55.05 79.19,55.05 | 80.78,50.45 84.59,50.45
  pour Bottom (isolate 0.025, no thermals): 73.96,55.53 74.91,55.53 74.91,56.64 75.7,57.43 74.75,57.43 73.96,56.64
  pour Bottom: 80.78,50.45 80.78,53.46 82.53,51.72 84.12,51.72 84.59,51.24 84.59,50.45
  pour Bottom (no thermals): 80.94,52.51 79.2,54.26 79.2,56 77.77,57.43 78.24,57.43 79.83,55.84 79.83,54.42 80.94,53.3
VIN
  Bottom 0.6: IC2.IN 6.17,24.73 13.79,24.73 21.73,16.79 29.03,16.79 | D1.C 27.48,12.07 29.03,13.62 29.03,16.79 | C7.2 41.09,16.16 39.19,14.25 37.44,14.25 34.9,16.79 29.03,16.79 | 48.08,15.01 47.95,15.01 46.81,16.16 C7.2 | 48.08,15.01 C8.+ | POWER.6 50.87,9.56 50.54,9.89 50.55,10.83 48.08,13.3 48.08,15.01 | 48.08,15.01 48.08,15.05
  pour Bottom (no thermals): 6.81,23.78 14.74,23.78 13.79,24.73 6.81,24.73
  pour Bottom: 41.65,16.71 48.56,16.71 50.54,14.73 50.54,10.6 49.43,11.71 46.33,11.71 42.37,15.68 40.62,15.68
  pour Bottom: 27.76,16.79 29.03,15.52 29.03,13.62 30.62,15.21 30.62,16 31.41,16.79

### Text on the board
tNames: PIN 0/1 | SERIAL | www.arduino.cc | GND REF | ENABLE | PWM | (PWM-AT168) | AREF | 0V | 13 | 12 | 11 | 10 | 9 | 8 | 7 | 6 | 5 | 4 | 3 | 2 | 1 | 0 | TX | RX | 1 | SDA | SCL | 5V | 0 | 0 | 9V | 0 | 1 | 2 | 3 | 4 | 5 | NC | RST | ANALOG IN
bNames: JP2 | LED13 | JP1 | JP3 | Arduino | S3V.3 R2 | 2008
bValues: ENABLE
bRestrict: Arduino | R.2 | V.3 | S3 | Pin0/1 | 2008 | REF | GND | SERIAL | ON | www.arduino.cc | AKASHI | A. | BANZI | M. | AUTO | CUARTIELLES | D. | CC BY SA 2.5 | RESET | ENABLE | MARTINO | G. | IGOE | T. | ZAMBETTI | N. | MELLIS | D.
tCredits: ADILSON AKASHI | MASSIMO BANZI | DAVID CUARTIELLES | TOM IGOE | GIANLUCA MARTINO | DAVID A. MELLIS | NICHOLAS ZAMBETTI | Released under the Creative Commons Attribution Share-Alike 2.5 License | http://creativecommons.org/licenses/by-sa/2.5/
Cooper Text: A | 0 | 13 | 12 | 11 | 10 | 9 | 8 | 7 | 6 | 5 | 4 | 3 | 2 | 1 | 0 | 1 | R | 5 | 0 | 0 | 9 | 0 | 1 | 2 | 3 | 4 | 5 | Analog in
bCredits: ADILSON AKASHI | MASSIMO BANZI | DAVID CUARTIELLES | TOM IGOE | GIANLUCA MARTINO | DAVID A. MELLIS | NICHOLAS ZAMBETTI | Released under the Creative Commons Attribution Share-Alike 2.5 License | http://creativecommons.org/licenses/by-sa/2.5/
